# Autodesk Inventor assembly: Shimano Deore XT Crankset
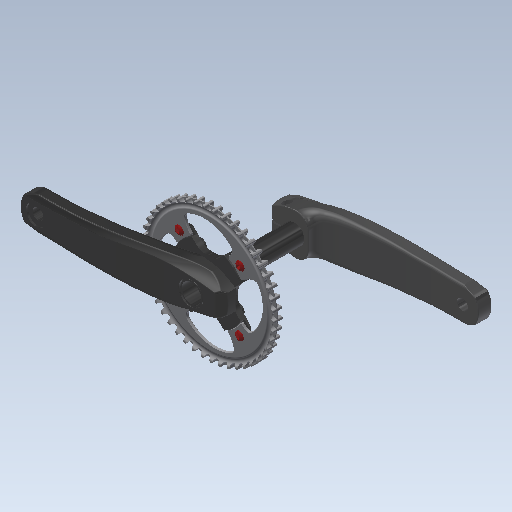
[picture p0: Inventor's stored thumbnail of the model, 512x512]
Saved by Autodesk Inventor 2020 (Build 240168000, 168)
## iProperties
Created: 2017-11
Part Number: Shimano Deore XT Crankset
Material: Ogólny
Document SubType Name: Assembly
Designer: Tomasz
Sending System: SolidWorks 2017
Last Author: Tomasz
Last Saved: 2017-11-19
Author: Tomasz
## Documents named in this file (6)
- C:\Users\bruno\Documents\1-Cours-2020-21\1STI2D-2020-21\IT\6. Antivol\Inventor-Antivol\INVENTOR 2018_Steel Hardtail B+\Shimano Deore XT Crankset.iam
- C:\Users\bruno\Documents\1-Cours-2020-21\1STI2D-2020-21\IT\6. Antivol\Inventor-Antivol\INVENTOR 2018_Steel Hardtail B+\Shimano Deore XT Crank.iam
- C:\Users\bruno\Documents\1-Cours-2020-21\1STI2D-2020-21\IT\6. Antivol\Inventor-Antivol\INVENTOR 2018_Steel Hardtail B+\Crank belt cog.ipt
- C:\Users\bruno\Documents\1-Cours-2020-21\1STI2D-2020-21\IT\6. Antivol\Inventor-Antivol\INVENTOR 2018_Steel Hardtail B+\nakrętka hollowtech 2.ipt
- C:\Users\bruno\Documents\1-Cours-2020-21\1STI2D-2020-21\IT\6. Antivol\Inventor-Antivol\INVENTOR 2018_Steel Hardtail B+\Śruba mocująca zębatkę.ipt
- C:\Users\bruno\Documents\1-Cours-2020-21\1STI2D-2020-21\IT\6. Antivol\Inventor-Antivol\INVENTOR 2018_Steel Hardtail B+\socket head cap screw_iso_ISO 4762 M6 x 25 - 25N.ipt
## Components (9 placed, 5 different names)
1. Shimano Deore XT Crank:1 [sub-assembly]
2. Crank belt cog:1
3. nakrętka hollowtech 2:1
4. Śruba mocująca zębatkę:1
5. Śruba mocująca zębatkę:2
6. Śruba mocująca zębatkę:3
7. Śruba mocująca zębatkę:4
8. socket head cap screw_iso:1
9. socket head cap screw_iso:2
